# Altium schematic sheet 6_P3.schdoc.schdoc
size 309 x 223 mm; Symbol: A4_Schematic_0605; Device: A4_Schematic_0605; @Project Name: MDIO-Board_Rev_01(0124); @Page Count: 10; @Update Date: 2024-06-05; @Create Date: 2024-05-19; @Schematic Name: Schematic1; @Page No: 3; @Page Name: P3
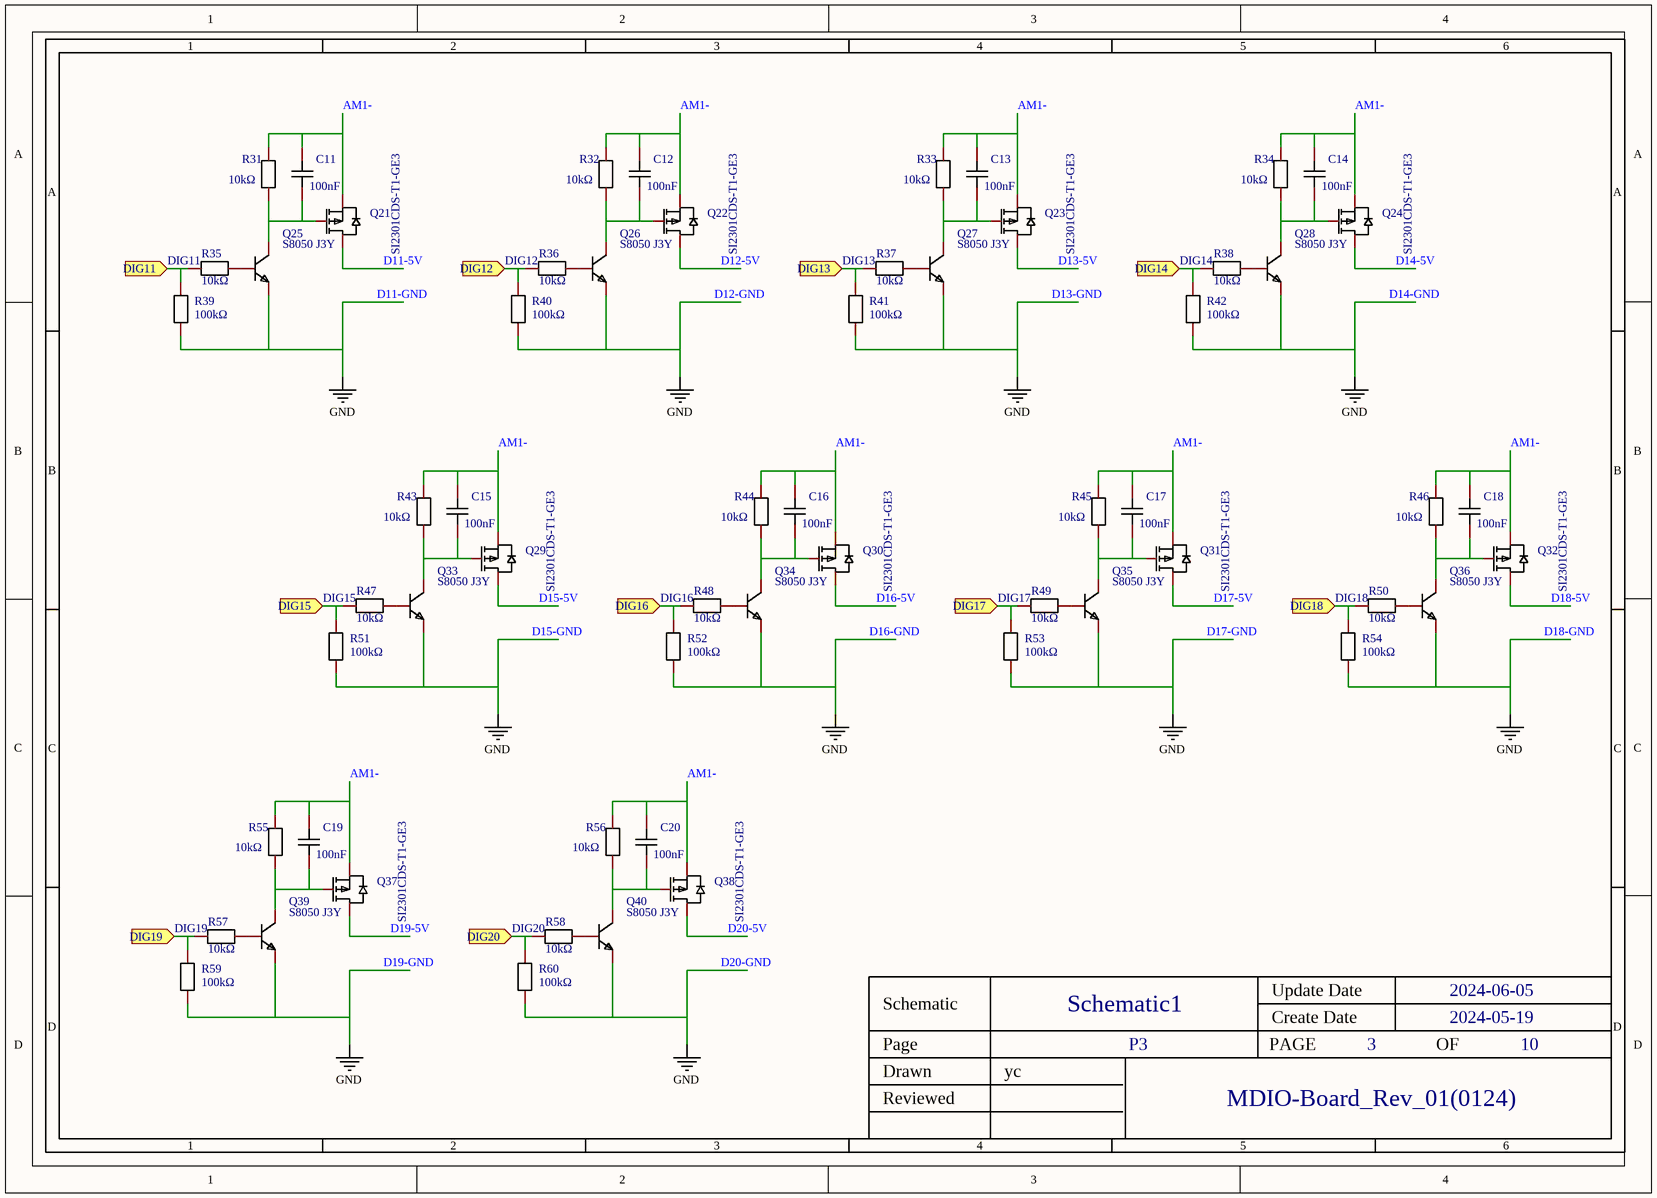
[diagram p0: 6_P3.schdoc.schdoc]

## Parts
C11  100nF  [C0603]
C12  100nF  [C0603]
C13  100nF  [C0603]
C14  100nF  [C0603]
C15  100nF  [C0603]
C16  100nF  [C0603]
C17  100nF  [C0603]
C18  100nF  [C0603]
C19  100nF  [C0603]
C20  100nF  [C0603]
Q21  SI2301CDS-T1-GE3  [SOT-23-3_L3.0-W1.7-P0.95-LS2.9-BR]
Q22  SI2301CDS-T1-GE3  [SOT-23-3_L3.0-W1.7-P0.95-LS2.9-BR]
Q23  SI2301CDS-T1-GE3  [SOT-23-3_L3.0-W1.7-P0.95-LS2.9-BR]
Q24  SI2301CDS-T1-GE3  [SOT-23-3_L3.0-W1.7-P0.95-LS2.9-BR]
Q25  S8050 J3Y  [SOT-23-3_L3.0-W1.7-P0.95-LS2.9-BR]
Q26  S8050 J3Y  [SOT-23-3_L3.0-W1.7-P0.95-LS2.9-BR]
Q27  S8050 J3Y  [SOT-23-3_L3.0-W1.7-P0.95-LS2.9-BR]
Q28  S8050 J3Y  [SOT-23-3_L3.0-W1.7-P0.95-LS2.9-BR]
Q29  SI2301CDS-T1-GE3  [SOT-23-3_L3.0-W1.7-P0.95-LS2.9-BR]
Q30  SI2301CDS-T1-GE3  [SOT-23-3_L3.0-W1.7-P0.95-LS2.9-BR]
Q31  SI2301CDS-T1-GE3  [SOT-23-3_L3.0-W1.7-P0.95-LS2.9-BR]
Q32  SI2301CDS-T1-GE3  [SOT-23-3_L3.0-W1.7-P0.95-LS2.9-BR]
Q33  S8050 J3Y  [SOT-23-3_L3.0-W1.7-P0.95-LS2.9-BR]
Q34  S8050 J3Y  [SOT-23-3_L3.0-W1.7-P0.95-LS2.9-BR]
Q35  S8050 J3Y  [SOT-23-3_L3.0-W1.7-P0.95-LS2.9-BR]
Q36  S8050 J3Y  [SOT-23-3_L3.0-W1.7-P0.95-LS2.9-BR]
Q37  SI2301CDS-T1-GE3  [SOT-23-3_L3.0-W1.7-P0.95-LS2.9-BR]
Q38  SI2301CDS-T1-GE3  [SOT-23-3_L3.0-W1.7-P0.95-LS2.9-BR]
Q39  S8050 J3Y  [SOT-23-3_L3.0-W1.7-P0.95-LS2.9-BR]
Q40  S8050 J3Y  [SOT-23-3_L3.0-W1.7-P0.95-LS2.9-BR]
R31  10kΩ  [R0603]
R32  10kΩ  [R0603]
R33  10kΩ  [R0603]
R34  10kΩ  [R0603]
R35  10kΩ  [R0603]
R36  10kΩ  [R0603]
R37  10kΩ  [R0603]
R38  10kΩ  [R0603]
R39  100kΩ  [R0603]
R40  100kΩ  [R0603]
R41  100kΩ  [R0603]
R42  100kΩ  [R0603]
R43  10kΩ  [R0603]
R44  10kΩ  [R0603]
R45  10kΩ  [R0603]
R46  10kΩ  [R0603]
R47  10kΩ  [R0603]
R48  10kΩ  [R0603]
R49  10kΩ  [R0603]
R50  10kΩ  [R0603]
R51  100kΩ  [R0603]
R52  100kΩ  [R0603]
R53  100kΩ  [R0603]
R54  100kΩ  [R0603]
R55  10kΩ  [R0603]
R56  10kΩ  [R0603]
R57  10kΩ  [R0603]
R58  10kΩ  [R0603]
R59  100kΩ  [R0603]
R60  100kΩ  [R0603]

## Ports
DIG11 (in), DIG12 (in), DIG13 (in), DIG14 (in), DIG15 (in), DIG16 (in), DIG17 (in), DIG18 (in), DIG19 (in), DIG20 (in)

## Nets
D11-GND: Q25.2(E) Q26.2(E) Q27.2(E) Q28.2(E) Q33.2(E) Q34.2(E) Q35.2(E) Q36.2(E) Q39.2(E) Q40.2(E) R39.1 R40.1 R41.1 R42.1 R51.1 R52.1 R53.1 R54.1 R59.1 R60.1  [also labelled D12-GND, D13-GND, D14-GND, D15-GND, D16-GND, D17-GND, D18-GND, D19-GND, D20-GND, GND]
AM1-: C11.1 C12.1 C13.1 C14.1 C15.1 C16.1 C17.1 C18.1 C19.1 C20.1 Q21.2(S) Q22.2(S) Q23.2(S) Q24.2(S) Q29.2(S) Q30.2(S) Q31.2(S) Q32.2(S) Q37.2(S) Q38.2(S) R31.2 R32.2 R33.2 R34.2 R43.2 R44.2 R45.2 R46.2 R55.2 R56.2
D11-5V: Q21.3(D)
D12-5V: Q22.3(D)
D13-5V: Q23.3(D)
D14-5V: Q24.3(D)
D15-5V: Q29.3(D)
D16-5V: Q30.3(D)
D17-5V: Q31.3(D)
D18-5V: Q32.3(D)
D19-5V: Q37.3(D)
D20-5V: Q38.3(D)
DIG11: R35.2 R39.2 ; port DIG11
DIG12: R36.2 R40.2 ; port DIG12
DIG13: R37.2 R41.2 ; port DIG13
DIG14: R38.2 R42.2 ; port DIG14
DIG15: R47.2 R51.2 ; port DIG15
DIG16: R48.2 R52.2 ; port DIG16
DIG17: R49.2 R53.2 ; port DIG17
DIG18: R50.2 R54.2 ; port DIG18
DIG19: R57.2 R59.2 ; port DIG19
DIG20: R58.2 R60.2 ; port DIG20
NetC11_2: C11.2 Q21.1(G) Q25.3(C) R31.1
NetC12_2: C12.2 Q22.1(G) Q26.3(C) R32.1
NetC13_2: C13.2 Q23.1(G) Q27.3(C) R33.1
NetC14_2: C14.2 Q24.1(G) Q28.3(C) R34.1
NetC15_2: C15.2 Q29.1(G) Q33.3(C) R43.1
NetC16_2: C16.2 Q30.1(G) Q34.3(C) R44.1
NetC17_2: C17.2 Q31.1(G) Q35.3(C) R45.1
NetC18_2: C18.2 Q32.1(G) Q36.3(C) R46.1
NetC19_2: C19.2 Q37.1(G) Q39.3(C) R55.1
NetC20_2: C20.2 Q38.1(G) Q40.3(C) R56.1
NetQ25_1: Q25.1(B) R35.1
NetQ26_1: Q26.1(B) R36.1
NetQ27_1: Q27.1(B) R37.1
NetQ28_1: Q28.1(B) R38.1
NetQ33_1: Q33.1(B) R47.1
NetQ34_1: Q34.1(B) R48.1
NetQ35_1: Q35.1(B) R49.1
NetQ36_1: Q36.1(B) R50.1
NetQ39_1: Q39.1(B) R57.1
NetQ40_1: Q40.1(B) R58.1

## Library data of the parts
C11-C20 = CC0603KRX7R9BB104: Manufacturer: YAGEO(国巨); Add into BOM: yes; Tolerance: ±10%; Description: Capacitance: Tolerance:±10% Tolerance:±10% Voltage Rated: Temperature Coefficient:
Q21-Q24 Q29-Q32 Q37 Q38 = SI2301CDS-T1-GE3: Manufacturer: VISHAY(威世); Add into BOM: yes; Type: 1个PChannel; Power Dissipation (Pd): ；; Drain Source On Resistance (RDS(on)@Vgs,Id): 112mΩ@4.5V,2.8A; Gate Threshold Voltage (Vgs(th)@Id): 1V@250uA; Total Gate Charge (Qg@Vgs): 10nC@4.5V; Input Capacitance (Ciss@Vds): 405pF@10V; Description: Type:1个PChannel Drain Source Voltage (Vdss): Continuous Drain Current (Id): Power Dissipation (Pd):； Drain Source On Resistance (RDS(on)@Vgs,Id):112mΩ@4.5V,2.8A Gate Threshold Voltage (Vgs(th)@Id):1V@250uA Total Gate Charge (Qg@Vgs):10nC@4.5V Input Capaci
Q25-Q28 Q33-Q36 Q39 Q40 = S8050 J3Y_C2146: Manufacturer: CJ(江苏长电/长晶); Symbol: S8050_C2146; Add into BOM: yes; DC Current Gain (hFE@Ic,Vce): 200@50mA,1V; Transition Frequency (fT): 150MHz; Collector Cut-Off Current (Icbo): 100nA; Collector-Emitter Saturation Voltage (VCE(sat)@Ic,Ib): 600mV@500mA,50mA; Description: Transistor Type: Collector Current (Ic): Collector-Emitter Breakdown Voltage (Vceo): Power Dissipation (Pd): DC Current Gain (hFE@Ic,Vce):200@50mA,1V DC Current Gain (hFE@Ic,Vce):200@50mA,1V Transition Frequency (fT):150MHz Collector Cut-Off Current (Icbo
R31-R38 R43-R50 R55-R58 = SCR0603J10K: Manufacturer: VO(翔胜); Add into BOM: yes; Tolerance: ±5%; Description: Type:Thick Film Resistors Resistance: Tolerance:±5% Tolerance:±5% Power(Watts): Overload Voltage (Max): Operating Temperature Range:-55℃~+155℃ Operating Temperature Range:-55℃~+155℃
R39-R42 R51-R54 R59 R60 = SCR0603F100K: Manufacturer: VO(翔胜); Add into BOM: yes; Tolerance: ±1%; Description: Type:Thick Film Resistors Resistance: Tolerance:±1% Tolerance:±1% Power(Watts): Overload Voltage (Max): Operating Temperature Range:-55℃~+155℃ Operating Temperature Range:-55℃~+155℃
